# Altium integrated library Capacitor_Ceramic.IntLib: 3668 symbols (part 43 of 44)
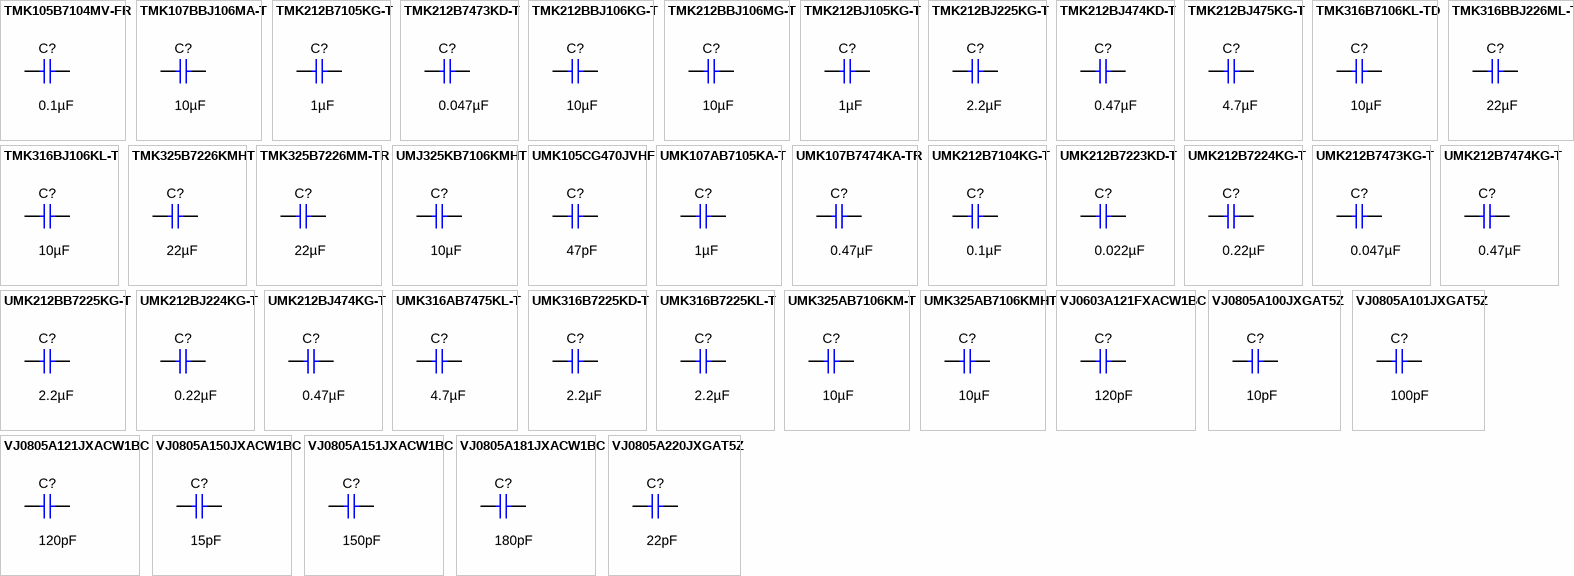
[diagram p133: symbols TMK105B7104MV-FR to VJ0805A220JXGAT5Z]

## UMK212BJ224KG-T
designator C?  ValueDisplayed: 0.22µF  (hidden comment: UMK212BJ224KG-T)
CAP, CERM, 0.22 µF, 50 V,+/- 10%, X5R, 0805; Manufacturer: Taiyo Yuden; Polarized: N; CompType: Capacitor; Value: 0.22uF; U/M: EA; Cap_F: 0.00000022; Tolerance_%: 10; VDC_V: 50; Value2: 50V; TaMin_C: -55; TaMax_C: 85; Cap_Case: 0805; SizeArea_mm2: 2.5; SizeAreaWB_mm2: 6.75; SizeX_mm: 2; SizeY_mm: 1.25; SizeZ_mm: 1.45; AEC Category: Q200; Green_Lifecycle: Active; Green_REACh: Passed
signal-integrity model Cap
simulation model Cap
footprint 0805_HV
footprint 0805_HV1
footprint 0805
footprint 0805M
footprint 0805L
pins: 1, 2

## UMK212BJ474KG-T
designator C?  ValueDisplayed: 0.47µF  (hidden comment: UMK212BJ474KG-T)
CAP, CERM, 0.47 µF, 50 V,+/- 10%, X5R, 0805; Manufacturer: Taiyo Yuden; Polarized: N; CompType: Capacitor; Value: 0.47uF; U/M: EA; Cap_F: 0.00000047; Tolerance_%: 10; VDC_V: 50; Value2: 50V; TaMin_C: -55; TaMax_C: 85; Cap_Case: 0805; SizeArea_mm2: 2.5; SizeAreaWB_mm2: 6.75; SizeX_mm: 2; SizeY_mm: 1.25; SizeZ_mm: 1.45; AEC Category: Q200
signal-integrity model Cap
simulation model Cap
footprint 0805_HV
footprint 0805_HV1
footprint 0805
footprint 0805M
footprint 0805L
pins: 1, 2

## UMK316AB7475KL-T
designator C?  ValueDisplayed: 4.7µF  (hidden comment: UMK316AB7475KL-T)
CAP, CERM, 4.7 µF, 50 V,+/- 10%, X7R, 1206; Manufacturer: Taiyo Yuden; Polarized: N; CompType: Capacitor; Value: 4.7uF; U/M: EA; Cap_F: 0.0000047; Tolerance_%: 10; VDC_V: 50; Value2: 50V; TaMin_C: -55; TaMax_C: 125; Cap_Case: 1206; SizeArea_mm2: 5.12; SizeAreaWB_mm2: 10.92; SizeX_mm: 3.2; SizeY_mm: 1.6; SizeZ_mm: 1.9; AEC Category: Q200; Green_Lifecycle: Active; Green_REACh: Passed
signal-integrity model Cap
simulation model Cap
footprint 1206_190
footprint 1206_190M
footprint 1206_190L
pins: 1, 2

## UMK316B7225KD-T
designator C?  ValueDisplayed: 2.2µF  (hidden comment: UMK316B7225KD-T)
CAP, CERM, 2.2 µF, 50 V,+/- 10%, X7R, 1206; Manufacturer: Taiyo Yuden; Polarized: N; CompType: Capacitor; Value: 2.2uF; U/M: EA; Cap_F: 0.0000022; Tolerance_%: 10; VDC_V: 50; Value2: 50V; TaMin_C: -55; TaMax_C: 125; Cap_Case: 1206; SizeArea_mm2: 5.12; SizeAreaWB_mm2: 10.92; SizeX_mm: 3.2; SizeY_mm: 1.6; SizeZ_mm: 1.35; AEC Category: Q200
signal-integrity model Cap
simulation model Cap
footprint 1206
footprint 1206M
footprint 1206L
pins: 1, 2

## UMK316B7225KL-T
designator C?  ValueDisplayed: 2.2µF  (hidden comment: UMK316B7225KL-T)
CAP, CERM, 2.2 µF, 50 V,+/- 10%, X7R, 1206; Manufacturer: Taiyo Yuden; Polarized: N; CompType: Capacitor; Value: 2.2uF; U/M: EA; Cap_F: 0.0000022; Tolerance_%: 10; VDC_V: 50; Value2: 50V; TaMin_C: -55; TaMax_C: 125; Cap_Case: 1206; SizeArea_mm2: 5.12; SizeAreaWB_mm2: 10.92; SizeX_mm: 3.2; SizeY_mm: 1.6; SizeZ_mm: 1.35; AEC Category: Q200
signal-integrity model Cap
simulation model Cap
footprint 1206
footprint 1206M
footprint 1206L
pins: 1, 2

## UMK325AB7106KM-T
designator C?  ValueDisplayed: 10µF  (hidden comment: UMK325AB7106KM-T)
CAP, CERM, 10 µF, 50 V,+/- 10%, X7R, 1210; Manufacturer: Taiyo Yuden; Polarized: N; CompType: Capacitor; Value: 10uF; U/M: EA; Cap_F: 0.00001; Tolerance_%: 10; VDC_V: 50; Value2: 50V; TaMin_C: -55; TaMax_C: 125; Cap_Case: 1210; SizeArea_mm2: 8; SizeAreaWB_mm2: 14.7; SizeX_mm: 3.2; SizeY_mm: 2.5; SizeZ_mm: 2.8; AEC Category: Q200; Green_Lifecycle: Active; Green_REACh: Passed
signal-integrity model Cap
simulation model Cap
footprint 1210_280
pins: 1, 2

## UMK325AB7106KMHT
designator C?  ValueDisplayed: 10µF  (hidden comment: UMK325AB7106KMHT)
CAP, CERM, 10 µF, 50 V,+/- 10%, X7R, AEC-Q200 Grade 1, 1210; Manufacturer: Taiyo Yuden; Polarized: N; CompType: Capacitor; Value: 10uF; U/M: EA; Cap_F: 0.00001; Tolerance_%: 10; VDC_V: 50; Value2: 50V; TaMin_C: -55; TaMax_C: 125; Cap_Case: 1210; SizeArea_mm2: 8; SizeAreaWB_mm2: 14.7; SizeX_mm: 3.2; SizeY_mm: 2.5; SizeZ_mm: 2.8; AEC Category: Q200; AEC Qualified: Y; AEC Grade: 1
signal-integrity model Cap
simulation model Cap
footprint 1210_280
pins: 1, 2

## VJ0603A121FXACW1BC
designator C?  ValueDisplayed: 120pF  (hidden comment: VJ0603A121FXACW1BC)
CAP, CERM, 120 pF, 50 V,+/- 1%, C0G/NP0, 0603; Manufacturer: Vishay-Sprague; Polarized: N; CompType: Capacitor; Value: 120pF; U/M: EA; Cap_F: 0.00000000012; Tolerance_%: 1; VDC_V: 50; Value2: 50V; TaMin_C: -55; TaMax_C: 125; Cap_Case: 0603; SizeArea_mm2: 1.28; SizeAreaWB_mm2: 4.68; SizeX_mm: 1.6; SizeY_mm: 0.8; AEC Category: Q200
signal-integrity model Cap
simulation model Cap
footprint 0603
footprint 0603M
footprint 0603L
footprint 0603_HV
footprint 0603S
pins: 1, 2

## VJ0805A100JXGAT5Z
designator C?  ValueDisplayed: 10pF  (hidden comment: VJ0805A100JXGAT5Z)
CAP, CERM, 10 pF, 1000 V,+/- 5%, C0G/NP0, 0805; Manufacturer: Vishay-Vitramon; Polarized: N; CompType: Capacitor; Value: 10pF; U/M: EA; Cap_F: 0.00000000001; Tolerance_%: 5; VDC_V: 1000; Value2: 1000V; TaMin_C: -55; TaMax_C: 125; Cap_Case: 0805; SizeArea_mm2: 2.5; SizeAreaWB_mm2: 6.75; SizeX_mm: 2; SizeY_mm: 1.25; SizeZ_mm: 1.45; AEC Category: Q200
signal-integrity model Cap
simulation model Cap
footprint 0805_HV
footprint 0805_HV1
footprint 0805
footprint 0805M
footprint 0805L
pins: 1, 2

## VJ0805A101JXGAT5Z
designator C?  ValueDisplayed: 100pF  (hidden comment: VJ0805A101JXGAT5Z)
CAP, CERM, 100 pF, 1000 V,+/- 5%, C0G/NP0, 0805; Manufacturer: Vishay-Vitramon; Polarized: N; CompType: Capacitor; Value: 100pF; U/M: EA; Cap_F: 0.0000000001; Tolerance_%: 5; VDC_V: 1000; Value2: 1000V; TaMin_C: -55; TaMax_C: 125; Cap_Case: 0805; SizeArea_mm2: 2.5; SizeAreaWB_mm2: 6.75; SizeX_mm: 2; SizeY_mm: 1.25; SizeZ_mm: 1.45; AEC Category: Q200
signal-integrity model Cap
simulation model Cap
footprint 0805_HV
footprint 0805_HV1
footprint 0805
footprint 0805M
footprint 0805L
pins: 1, 2

## VJ0805A121JXACW1BC
designator C?  ValueDisplayed: 120pF  (hidden comment: VJ0805A121JXACW1BC)
CAP, CERM, 120 pF, 50 V,+/- 5%, C0G/NP0, 0805; Manufacturer: Vishay-Bccomponents; Polarized: N; CompType: Capacitor; Value: 120pF; U/M: EA; Cap_F: 0.00000000012; Tolerance_%: 5; VDC_V: 50; Value2: 50V; TaMin_C: -55; TaMax_C: 125; Cap_Case: 0805; SizeArea_mm2: 2.5; SizeAreaWB_mm2: 6.75; SizeX_mm: 2; SizeY_mm: 1.25; SizeZ_mm: 1.45; AEC Category: Q200
signal-integrity model Cap
simulation model Cap
footprint 0805_HV
footprint 0805_HV1
footprint 0805
footprint 0805M
footprint 0805L
pins: 1, 2

## VJ0805A150JXACW1BC
designator C?  ValueDisplayed: 15pF  (hidden comment: VJ0805A150JXACW1BC)
CAP, CERM, 15 pF, 50 V,+/- 5%, C0G/NP0, 0805; Manufacturer: Vishay-Bccomponents; Polarized: N; CompType: Capacitor; Value: 15pF; U/M: EA; Cap_F: 0.000000000015; Tolerance_%: 5; VDC_V: 50; Value2: 50V; TaMin_C: -55; TaMax_C: 125; Cap_Case: 0805; SizeArea_mm2: 2.5; SizeAreaWB_mm2: 6.75; SizeX_mm: 2; SizeY_mm: 1.25; SizeZ_mm: 1.45; AEC Category: Q200
signal-integrity model Cap
simulation model Cap
footprint 0805_HV
footprint 0805_HV1
footprint 0805
footprint 0805M
footprint 0805L
pins: 1, 2

## VJ0805A151JXACW1BC
designator C?  ValueDisplayed: 150pF  (hidden comment: VJ0805A151JXACW1BC)
CAP, CERM, 150 pF, 50 V,+/- 5%, C0G/NP0, 0805; Manufacturer: Vishay-Bccomponents; Polarized: N; CompType: Capacitor; Value: 150pF; U/M: EA; Cap_F: 0.00000000015; Tolerance_%: 5; VDC_V: 50; Value2: 50V; TaMin_C: -55; TaMax_C: 125; Cap_Case: 0805; SizeArea_mm2: 2.5; SizeAreaWB_mm2: 6.75; SizeX_mm: 2; SizeY_mm: 1.25; SizeZ_mm: 1.45; AEC Category: Q200
signal-integrity model Cap
simulation model Cap
footprint 0805_HV
footprint 0805_HV1
footprint 0805
footprint 0805M
footprint 0805L
pins: 1, 2

## VJ0805A181JXACW1BC
designator C?  ValueDisplayed: 180pF  (hidden comment: VJ0805A181JXACW1BC)
CAP, CERM, 180 pF, 50 V,+/- 5%, C0G/NP0, 0805; Manufacturer: Vishay-Bccomponents; Polarized: N; CompType: Capacitor; Value: 180pF; U/M: EA; Cap_F: 0.00000000018; Tolerance_%: 5; VDC_V: 50; Value2: 50V; TaMin_C: -55; TaMax_C: 125; Cap_Case: 0805; SizeArea_mm2: 2.5; SizeAreaWB_mm2: 6.75; SizeX_mm: 2; SizeY_mm: 1.25; SizeZ_mm: 1.45; AEC Category: Q200
signal-integrity model Cap
simulation model Cap
footprint 0805_HV
footprint 0805_HV1
footprint 0805
footprint 0805M
footprint 0805L
pins: 1, 2

## VJ0805A220JXGAT5Z
designator C?  ValueDisplayed: 22pF  (hidden comment: VJ0805A220JXGAT5Z)
CAP, CERM, 22 pF, 1000 V,+/- 5%, C0G/NP0, 0805; Manufacturer: Vishay-Vitramon; Polarized: N; CompType: Capacitor; Value: 22pF; U/M: EA; Cap_F: 0.000000000022; Tolerance_%: 5; VDC_V: 1000; Value2: 1000V; TaMin_C: -55; TaMax_C: 125; Cap_Case: 0805; SizeArea_mm2: 2.5; SizeAreaWB_mm2: 6.75; SizeX_mm: 2; SizeY_mm: 1.25; SizeZ_mm: 1.45; AEC Category: Q200
signal-integrity model Cap
simulation model Cap
footprint 0805_HV
footprint 0805_HV1
footprint 0805
footprint 0805M
footprint 0805L
pins: 1, 2

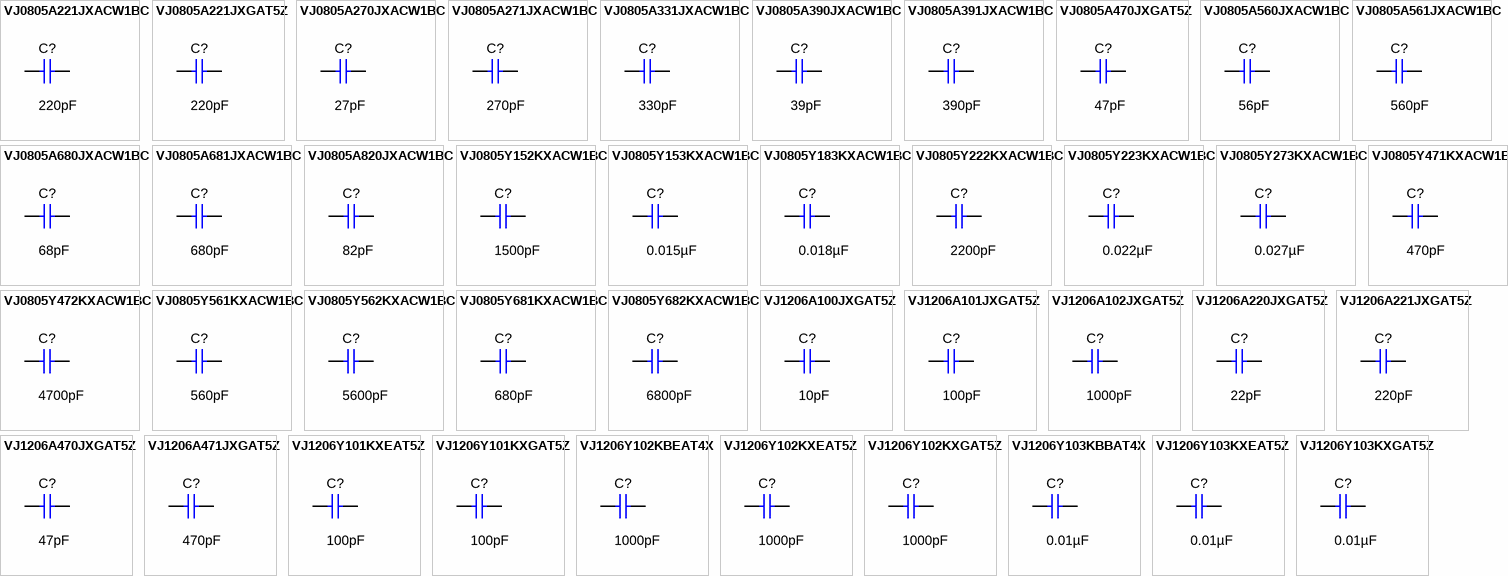
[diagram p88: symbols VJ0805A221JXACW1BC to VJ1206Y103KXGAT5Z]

## VJ0805A221JXACW1BC
designator C?  ValueDisplayed: 220pF  (hidden comment: VJ0805A221JXACW1BC)
CAP, CERM, 220 pF, 50 V,+/- 5%, C0G/NP0, 0805; Manufacturer: Vishay-Bccomponents; Polarized: N; CompType: Capacitor; Value: 220pF; U/M: EA; Cap_F: 0.00000000022; Tolerance_%: 5; VDC_V: 50; Value2: 50V; TaMin_C: -55; TaMax_C: 125; Cap_Case: 0805; SizeArea_mm2: 2.5; SizeAreaWB_mm2: 6.75; SizeX_mm: 2; SizeY_mm: 1.25; SizeZ_mm: 1.45; AEC Category: Q200
signal-integrity model Cap
simulation model Cap
footprint 0805_HV
footprint 0805_HV1
footprint 0805
footprint 0805M
footprint 0805L
pins: 1, 2

## VJ0805A221JXGAT5Z
designator C?  ValueDisplayed: 220pF  (hidden comment: VJ0805A221JXGAT5Z)
CAP, CERM, 220 pF, 1000 V,+/- 5%, C0G/NP0, 0805; Manufacturer: Vishay-Vitramon; Polarized: N; CompType: Capacitor; Value: 220pF; U/M: EA; Cap_F: 0.00000000022; Tolerance_%: 5; VDC_V: 1000; Value2: 1000V; TaMin_C: -55; TaMax_C: 125; Cap_Case: 0805; SizeArea_mm2: 2.5; SizeAreaWB_mm2: 6.75; SizeX_mm: 2; SizeY_mm: 1.25; SizeZ_mm: 1.45; AEC Category: Q200
signal-integrity model Cap
simulation model Cap
footprint 0805_HV
footprint 0805_HV1
footprint 0805
footprint 0805M
footprint 0805L
pins: 1, 2

## VJ0805A270JXACW1BC
designator C?  ValueDisplayed: 27pF  (hidden comment: VJ0805A270JXACW1BC)
CAP, CERM, 27 pF, 50 V,+/- 5%, C0G/NP0, 0805; Manufacturer: Vishay-Bccomponents; Polarized: N; CompType: Capacitor; Value: 27pF; U/M: EA; Cap_F: 0.000000000027; Tolerance_%: 5; VDC_V: 50; Value2: 50V; TaMin_C: -55; TaMax_C: 125; Cap_Case: 0805; SizeArea_mm2: 2.5; SizeAreaWB_mm2: 6.75; SizeX_mm: 2; SizeY_mm: 1.25; SizeZ_mm: 1.45; AEC Category: Q200
signal-integrity model Cap
simulation model Cap
footprint 0805_HV
footprint 0805_HV1
footprint 0805
footprint 0805M
footprint 0805L
pins: 1, 2

## VJ0805A271JXACW1BC
designator C?  ValueDisplayed: 270pF  (hidden comment: VJ0805A271JXACW1BC)
CAP, CERM, 270 pF, 50 V,+/- 5%, C0G/NP0, 0805; Manufacturer: Vishay-Bccomponents; Polarized: N; CompType: Capacitor; Value: 270pF; U/M: EA; Cap_F: 0.00000000027; Tolerance_%: 5; VDC_V: 50; Value2: 50V; TaMin_C: -55; TaMax_C: 125; Cap_Case: 0805; SizeArea_mm2: 2.5; SizeAreaWB_mm2: 6.75; SizeX_mm: 2; SizeY_mm: 1.25; SizeZ_mm: 1.45; AEC Category: Q200; Green_Lifecycle: Not Set; Green_REACh: Incomplete
signal-integrity model Cap
simulation model Cap
footprint 0805_HV
footprint 0805_HV1
footprint 0805
footprint 0805M
footprint 0805L
pins: 1, 2

## VJ0805A331JXACW1BC
designator C?  ValueDisplayed: 330pF  (hidden comment: VJ0805A331JXACW1BC)
CAP, CERM, 330 pF, 50 V,+/- 5%, C0G/NP0, 0805; Manufacturer: Vishay-Bccomponents; Polarized: N; CompType: Capacitor; Value: 330pF; U/M: EA; Cap_F: 0.00000000033; Tolerance_%: 5; VDC_V: 50; Value2: 50V; TaMin_C: -55; TaMax_C: 125; Cap_Case: 0805; SizeArea_mm2: 2.5; SizeAreaWB_mm2: 6.75; SizeX_mm: 2; SizeY_mm: 1.25; SizeZ_mm: 1.45; AEC Category: Q200
signal-integrity model Cap
simulation model Cap
footprint 0805_HV
footprint 0805_HV1
footprint 0805
footprint 0805M
footprint 0805L
pins: 1, 2

## VJ0805A390JXACW1BC
designator C?  ValueDisplayed: 39pF  (hidden comment: VJ0805A390JXACW1BC)
CAP, CERM, 39 pF, 50 V,+/- 5%, C0G/NP0, 0805; Manufacturer: Vishay-Bccomponents; Polarized: N; CompType: Capacitor; Value: 39pF; U/M: EA; Cap_F: 0.000000000039; Tolerance_%: 5; VDC_V: 50; Value2: 50V; TaMin_C: -55; TaMax_C: 125; Cap_Case: 0805; SizeArea_mm2: 2.5; SizeAreaWB_mm2: 6.75; SizeX_mm: 2; SizeY_mm: 1.25; SizeZ_mm: 1.45; AEC Category: Q200
signal-integrity model Cap
simulation model Cap
footprint 0805_HV
footprint 0805_HV1
footprint 0805
footprint 0805M
footprint 0805L
pins: 1, 2

## VJ0805A391JXACW1BC
designator C?  ValueDisplayed: 390pF  (hidden comment: VJ0805A391JXACW1BC)
CAP, CERM, 390 pF, 50 V,+/- 5%, C0G/NP0, 0805; Manufacturer: Vishay-Bccomponents; Polarized: N; CompType: Capacitor; Value: 390pF; U/M: EA; Cap_F: 0.00000000039; Tolerance_%: 5; VDC_V: 50; Value2: 50V; TaMin_C: -55; TaMax_C: 125; Cap_Case: 0805; SizeArea_mm2: 2.5; SizeAreaWB_mm2: 6.75; SizeX_mm: 2; SizeY_mm: 1.25; SizeZ_mm: 1.45; AEC Category: Q200
signal-integrity model Cap
simulation model Cap
footprint 0805_HV
footprint 0805_HV1
footprint 0805
footprint 0805M
footprint 0805L
pins: 1, 2

## VJ0805A470JXGAT5Z
designator C?  ValueDisplayed: 47pF  (hidden comment: VJ0805A470JXGAT5Z)
CAP, CERM, 47 pF, 1000 V,+/- 5%, C0G/NP0, 0805; Manufacturer: Vishay-Vitramon; Polarized: N; CompType: Capacitor; Value: 47pF; U/M: EA; Cap_F: 0.000000000047; Tolerance_%: 5; VDC_V: 1000; Value2: 1000V; TaMin_C: -55; TaMax_C: 125; Cap_Case: 0805; SizeArea_mm2: 2.5; SizeAreaWB_mm2: 6.75; SizeX_mm: 2; SizeY_mm: 1.25; SizeZ_mm: 1.45; AEC Category: Q200
signal-integrity model Cap
simulation model Cap
footprint 0805_HV
footprint 0805_HV1
footprint 0805
footprint 0805M
footprint 0805L
pins: 1, 2

## VJ0805A560JXACW1BC
designator C?  ValueDisplayed: 56pF  (hidden comment: VJ0805A560JXACW1BC)
CAP, CERM, 56 pF, 50 V,+/- 5%, C0G/NP0, 0805; Manufacturer: Vishay-Bccomponents; Polarized: N; CompType: Capacitor; Value: 56pF; U/M: EA; Cap_F: 0.000000000056; Tolerance_%: 5; VDC_V: 50; Value2: 50V; TaMin_C: -55; TaMax_C: 125; Cap_Case: 0805; SizeArea_mm2: 2.5; SizeAreaWB_mm2: 6.75; SizeX_mm: 2; SizeY_mm: 1.25; SizeZ_mm: 1.45; AEC Category: Q200
signal-integrity model Cap
simulation model Cap
footprint 0805_HV
footprint 0805_HV1
footprint 0805
footprint 0805M
footprint 0805L
pins: 1, 2

## VJ0805A561JXACW1BC
designator C?  ValueDisplayed: 560pF  (hidden comment: VJ0805A561JXACW1BC)
CAP, CERM, 560 pF, 50 V,+/- 5%, C0G/NP0, 0805; Manufacturer: Vishay-Bccomponents; Polarized: N; CompType: Capacitor; Value: 560pF; U/M: EA; Cap_F: 0.00000000056; Tolerance_%: 5; VDC_V: 50; Value2: 50V; TaMin_C: -55; TaMax_C: 125; Cap_Case: 0805; SizeArea_mm2: 2.5; SizeAreaWB_mm2: 6.75; SizeX_mm: 2; SizeY_mm: 1.25; SizeZ_mm: 1.45; AEC Category: Q200
signal-integrity model Cap
simulation model Cap
footprint 0805_HV
footprint 0805_HV1
footprint 0805
footprint 0805M
footprint 0805L
pins: 1, 2

## VJ0805A680JXACW1BC
designator C?  ValueDisplayed: 68pF  (hidden comment: VJ0805A680JXACW1BC)
CAP, CERM, 68 pF, 50 V,+/- 5%, C0G/NP0, 0805; Manufacturer: Vishay-Bccomponents; Polarized: N; CompType: Capacitor; Value: 68pF; U/M: EA; Cap_F: 0.000000000068; Tolerance_%: 5; VDC_V: 50; Value2: 50V; TaMin_C: -55; TaMax_C: 125; Cap_Case: 0805; SizeArea_mm2: 2.5; SizeAreaWB_mm2: 6.75; SizeX_mm: 2; SizeY_mm: 1.25; SizeZ_mm: 1.45; AEC Category: Q200
signal-integrity model Cap
simulation model Cap
footprint 0805_HV
footprint 0805_HV1
footprint 0805
footprint 0805M
footprint 0805L
pins: 1, 2

## VJ0805A681JXACW1BC
designator C?  ValueDisplayed: 680pF  (hidden comment: VJ0805A681JXACW1BC)
CAP, CERM, 680 pF, 50 V,+/- 5%, C0G/NP0, 0805; Manufacturer: Vishay-Bccomponents; Polarized: N; CompType: Capacitor; Value: 680pF; U/M: EA; Cap_F: 0.00000000068; Tolerance_%: 5; VDC_V: 50; Value2: 50V; TaMin_C: -55; TaMax_C: 125; Cap_Case: 0805; SizeArea_mm2: 2.5; SizeAreaWB_mm2: 6.75; SizeX_mm: 2; SizeY_mm: 1.25; SizeZ_mm: 1.45; AEC Category: Q200
signal-integrity model Cap
simulation model Cap
footprint 0805_HV
footprint 0805_HV1
footprint 0805
footprint 0805M
footprint 0805L
pins: 1, 2

## VJ0805A820JXACW1BC
designator C?  ValueDisplayed: 82pF  (hidden comment: VJ0805A820JXACW1BC)
CAP, CERM, 82 pF, 50 V,+/- 5%, C0G/NP0, 0805; Manufacturer: Vishay-Bccomponents; Polarized: N; CompType: Capacitor; Value: 82pF; U/M: EA; Cap_F: 0.000000000082; Tolerance_%: 5; VDC_V: 50; Value2: 50V; TaMin_C: -55; TaMax_C: 125; Cap_Case: 0805; SizeArea_mm2: 2.5; SizeAreaWB_mm2: 6.75; SizeX_mm: 2; SizeY_mm: 1.25; SizeZ_mm: 1.45; AEC Category: Q200
signal-integrity model Cap
simulation model Cap
footprint 0805_HV
footprint 0805_HV1
footprint 0805
footprint 0805M
footprint 0805L
pins: 1, 2

## VJ0805Y152KXACW1BC
designator C?  ValueDisplayed: 1500pF  (hidden comment: VJ0805Y152KXACW1BC)
CAP, CERM, 1500 pF, 50 V,+/- 10%, X7R, 0805; Manufacturer: Vishay-Bccomponents; Polarized: N; CompType: Capacitor; Value: 1500pF; U/M: EA; Cap_F: 0.0000000015; Tolerance_%: 10; VDC_V: 50; Value2: 50V; TaMin_C: -55; TaMax_C: 125; Cap_Case: 0805; SizeArea_mm2: 2.5; SizeAreaWB_mm2: 6.75; SizeX_mm: 2; SizeY_mm: 1.25; SizeZ_mm: 1.45; AEC Category: Q200
signal-integrity model Cap
simulation model Cap
footprint 0805_HV
footprint 0805_HV1
footprint 0805
footprint 0805M
footprint 0805L
pins: 1, 2

## VJ0805Y153KXACW1BC
designator C?  ValueDisplayed: 0.015µF  (hidden comment: VJ0805Y153KXACW1BC)
CAP, CERM, 0.015 µF, 50 V,+/- 10%, X7R, 0805; Manufacturer: Vishay-Bccomponents; Polarized: N; CompType: Capacitor; Value: 0.015uF; U/M: EA; Cap_F: 0.000000015; Tolerance_%: 10; VDC_V: 50; Value2: 50V; TaMin_C: -55; TaMax_C: 125; Cap_Case: 0805; SizeArea_mm2: 2.5; SizeAreaWB_mm2: 6.75; SizeX_mm: 2; SizeY_mm: 1.25; SizeZ_mm: 1.45; AEC Category: Q200
signal-integrity model Cap
simulation model Cap
footprint 0805_HV
footprint 0805_HV1
footprint 0805
footprint 0805M
footprint 0805L
pins: 1, 2

## VJ0805Y183KXACW1BC
designator C?  ValueDisplayed: 0.018µF  (hidden comment: VJ0805Y183KXACW1BC)
CAP, CERM, 0.018 µF, 50 V,+/- 10%, X7R, 0805; Manufacturer: Vishay-Bccomponents; Polarized: N; CompType: Capacitor; Value: 0.018uF; U/M: EA; Cap_F: 0.000000018; Tolerance_%: 10; VDC_V: 50; Value2: 50V; TaMin_C: -55; TaMax_C: 125; Cap_Case: 0805; SizeArea_mm2: 2.5; SizeAreaWB_mm2: 6.75; SizeX_mm: 2; SizeY_mm: 1.25; SizeZ_mm: 1.45; AEC Category: Q200
signal-integrity model Cap
simulation model Cap
footprint 0805_HV
footprint 0805_HV1
footprint 0805
footprint 0805M
footprint 0805L
pins: 1, 2

## VJ0805Y222KXACW1BC
designator C?  ValueDisplayed: 2200pF  (hidden comment: VJ0805Y222KXACW1BC)
CAP, CERM, 2200 pF, 50 V,+/- 10%, X7R, 0805; Manufacturer: Vishay-Bccomponents; Polarized: N; CompType: Capacitor; Value: 2200pF; U/M: EA; Cap_F: 0.0000000022; Tolerance_%: 10; VDC_V: 50; Value2: 50V; TaMin_C: -55; TaMax_C: 125; Cap_Case: 0805; SizeArea_mm2: 2.5; SizeAreaWB_mm2: 6.75; SizeX_mm: 2; SizeY_mm: 1.25; SizeZ_mm: 1.45; AEC Category: Q200
signal-integrity model Cap
simulation model Cap
footprint 0805_HV
footprint 0805_HV1
footprint 0805
footprint 0805M
footprint 0805L
pins: 1, 2

## VJ0805Y223KXACW1BC
designator C?  ValueDisplayed: 0.022µF  (hidden comment: VJ0805Y223KXACW1BC)
CAP, CERM, 0.022 µF, 50 V,+/- 10%, X7R, 0805; Manufacturer: Vishay-Bccomponents; Polarized: N; CompType: Capacitor; Value: 0.022uF; U/M: EA; Cap_F: 0.000000022; Tolerance_%: 10; VDC_V: 50; Value2: 50V; TaMin_C: -55; TaMax_C: 125; Cap_Case: 0805; SizeArea_mm2: 2.5; SizeAreaWB_mm2: 6.75; SizeX_mm: 2; SizeY_mm: 1.25; SizeZ_mm: 1.45; AEC Category: Q200
signal-integrity model Cap
simulation model Cap
footprint 0805_HV
footprint 0805_HV1
footprint 0805
footprint 0805M
footprint 0805L
pins: 1, 2

## VJ0805Y273KXACW1BC
designator C?  ValueDisplayed: 0.027µF  (hidden comment: VJ0805Y273KXACW1BC)
CAP, CERM, 0.027 µF, 50 V,+/- 10%, X7R, 0805; Manufacturer: Vishay-Bccomponents; Polarized: N; CompType: Capacitor; Value: 0.027uF; U/M: EA; Cap_F: 0.000000027; Tolerance_%: 10; VDC_V: 50; Value2: 50V; TaMin_C: -55; TaMax_C: 125; Cap_Case: 0805; SizeArea_mm2: 2.5; SizeAreaWB_mm2: 6.75; SizeX_mm: 2; SizeY_mm: 1.25; SizeZ_mm: 1.45; AEC Category: Q200
signal-integrity model Cap
simulation model Cap
footprint 0805_HV
footprint 0805_HV1
footprint 0805
footprint 0805M
footprint 0805L
pins: 1, 2

## VJ0805Y471KXACW1BC
designator C?  ValueDisplayed: 470pF  (hidden comment: VJ0805Y471KXACW1BC)
CAP, CERM, 470 pF, 50 V,+/- 10%, X7R, 0805; Manufacturer: Vishay-Bccomponents; Polarized: N; CompType: Capacitor; Value: 470pF; U/M: EA; Cap_F: 0.00000000047; Tolerance_%: 10; VDC_V: 50; Value2: 50V; TaMin_C: -55; TaMax_C: 125; Cap_Case: 0805; SizeArea_mm2: 2.5; SizeAreaWB_mm2: 6.75; SizeX_mm: 2; SizeY_mm: 1.25; SizeZ_mm: 1.45; AEC Category: Q200
signal-integrity model Cap
simulation model Cap
footprint 0805_HV
footprint 0805_HV1
footprint 0805
footprint 0805M
footprint 0805L
pins: 1, 2

## VJ0805Y472KXACW1BC
designator C?  ValueDisplayed: 4700pF  (hidden comment: VJ0805Y472KXACW1BC)
CAP, CERM, 4700 pF, 50 V,+/- 10%, X7R, 0805; Manufacturer: Vishay-Bccomponents; Polarized: N; CompType: Capacitor; Value: 4700pF; U/M: EA; Cap_F: 0.0000000047; Tolerance_%: 10; VDC_V: 50; Value2: 50V; TaMin_C: -55; TaMax_C: 125; Cap_Case: 0805; SizeArea_mm2: 2.5; SizeAreaWB_mm2: 6.75; SizeX_mm: 2; SizeY_mm: 1.25; SizeZ_mm: 1.45; AEC Category: Q200
signal-integrity model Cap
simulation model Cap
footprint 0805_HV
footprint 0805_HV1
footprint 0805
footprint 0805M
footprint 0805L
pins: 1, 2

## VJ0805Y561KXACW1BC
designator C?  ValueDisplayed: 560pF  (hidden comment: VJ0805Y561KXACW1BC)
CAP, CERM, 560 pF, 50 V,+/- 10%, X7R, 0805; Manufacturer: Vishay-Bccomponents; Polarized: N; CompType: Capacitor; Value: 560pF; U/M: EA; Cap_F: 0.00000000056; Tolerance_%: 10; VDC_V: 50; Value2: 50V; TaMin_C: -55; TaMax_C: 125; Cap_Case: 0805; SizeArea_mm2: 2.5; SizeAreaWB_mm2: 6.75; SizeX_mm: 2; SizeY_mm: 1.25; SizeZ_mm: 1.45; AEC Category: Q200; Green_Lifecycle: Active; Green_REACh: Passed
signal-integrity model Cap
simulation model Cap
footprint 0805_HV
footprint 0805_HV1
footprint 0805
footprint 0805M
footprint 0805L
pins: 1, 2

## VJ0805Y562KXACW1BC
designator C?  ValueDisplayed: 5600pF  (hidden comment: VJ0805Y562KXACW1BC)
CAP, CERM, 5600 pF, 50 V,+/- 10%, X7R, 0805; Manufacturer: Vishay-Bccomponents; Polarized: N; CompType: Capacitor; Value: 5600pF; U/M: EA; Cap_F: 0.0000000056; Tolerance_%: 10; VDC_V: 50; Value2: 50V; TaMin_C: -55; TaMax_C: 125; Cap_Case: 0805; SizeArea_mm2: 2.5; SizeAreaWB_mm2: 6.75; SizeX_mm: 2; SizeY_mm: 1.25; SizeZ_mm: 1.45; AEC Category: Q200
signal-integrity model Cap
simulation model Cap
footprint 0805_HV
footprint 0805_HV1
footprint 0805
footprint 0805M
footprint 0805L
pins: 1, 2

## VJ0805Y681KXACW1BC
designator C?  ValueDisplayed: 680pF  (hidden comment: VJ0805Y681KXACW1BC)
CAP, CERM, 680 pF, 50 V,+/- 10%, X7R, 0805; Manufacturer: Vishay-Bccomponents; Polarized: N; CompType: Capacitor; Value: 680pF; U/M: EA; Cap_F: 0.00000000068; Tolerance_%: 10; VDC_V: 50; Value2: 50V; TaMin_C: -55; TaMax_C: 125; Cap_Case: 0805; SizeArea_mm2: 2.5; SizeAreaWB_mm2: 6.75; SizeX_mm: 2; SizeY_mm: 1.25; SizeZ_mm: 1.45; AEC Category: Q200
signal-integrity model Cap
simulation model Cap
footprint 0805_HV
footprint 0805_HV1
footprint 0805
footprint 0805M
footprint 0805L
pins: 1, 2

## VJ0805Y682KXACW1BC
designator C?  ValueDisplayed: 6800pF  (hidden comment: VJ0805Y682KXACW1BC)
CAP, CERM, 6800 pF, 50 V,+/- 10%, X7R, 0805; Manufacturer: Vishay-Bccomponents; Polarized: N; CompType: Capacitor; Value: 6800pF; U/M: EA; Cap_F: 0.0000000068; Tolerance_%: 10; VDC_V: 50; Value2: 50V; TaMin_C: -55; TaMax_C: 125; Cap_Case: 0805; SizeArea_mm2: 2.5; SizeAreaWB_mm2: 6.75; SizeX_mm: 2; SizeY_mm: 1.25; SizeZ_mm: 1.45; AEC Category: Q200
signal-integrity model Cap
simulation model Cap
footprint 0805_HV
footprint 0805_HV1
footprint 0805
footprint 0805M
footprint 0805L
pins: 1, 2

## VJ1206A100JXGAT5Z
designator C?  ValueDisplayed: 10pF  (hidden comment: VJ1206A100JXGAT5Z)
CAP, CERM, 10 pF, 1000 V,+/- 5%, C0G/NP0, 1206; Manufacturer: Vishay-Vitramon; Polarized: N; CompType: Capacitor; Value: 10pF; U/M: EA; Cap_F: 0.00000000001; Tolerance_%: 5; VDC_V: 1000; Value2: 1000V; TaMin_C: -55; TaMax_C: 125; Cap_Case: 1206; SizeArea_mm2: 5.12; SizeAreaWB_mm2: 10.92; SizeX_mm: 3.2; SizeY_mm: 1.6; SizeZ_mm: 1.35; AEC Category: Q200
signal-integrity model Cap
simulation model Cap
footprint 1206
footprint 1206M
footprint 1206L
pins: 1, 2

## VJ1206A101JXGAT5Z
designator C?  ValueDisplayed: 100pF  (hidden comment: VJ1206A101JXGAT5Z)
CAP, CERM, 100 pF, 1000 V,+/- 5%, C0G/NP0, 1206; Manufacturer: Vishay-Vitramon; Polarized: N; CompType: Capacitor; Value: 100pF; U/M: EA; Cap_F: 0.0000000001; Tolerance_%: 5; VDC_V: 1000; Value2: 1000V; TaMin_C: -55; TaMax_C: 125; Cap_Case: 1206; SizeArea_mm2: 5.12; SizeAreaWB_mm2: 10.92; SizeX_mm: 3.2; SizeY_mm: 1.6; SizeZ_mm: 1.35; AEC Category: Q200
signal-integrity model Cap
simulation model Cap
footprint 1206
footprint 1206M
footprint 1206L
pins: 1, 2

## VJ1206A102JXGAT5Z
designator C?  ValueDisplayed: 1000pF  (hidden comment: VJ1206A102JXGAT5Z)
CAP, CERM, 1000 pF, 1000 V,+/- 5%, C0G/NP0, 1206; Manufacturer: Vishay-Vitramon; Polarized: N; CompType: Capacitor; Value: 1000pF; U/M: EA; Cap_F: 0.000000001; Tolerance_%: 5; VDC_V: 1000; Value2: 1000V; TaMin_C: -55; TaMax_C: 125; Cap_Case: 1206; SizeArea_mm2: 5.12; SizeAreaWB_mm2: 10.92; SizeX_mm: 3.2; SizeY_mm: 1.6; SizeZ_mm: 1.35; AEC Category: Q200
signal-integrity model Cap
simulation model Cap
footprint 1206
footprint 1206M
footprint 1206L
pins: 1, 2

## VJ1206A220JXGAT5Z
designator C?  ValueDisplayed: 22pF  (hidden comment: VJ1206A220JXGAT5Z)
CAP, CERM, 22 pF, 1000 V,+/- 5%, C0G/NP0, 1206; Manufacturer: Vishay-Vitramon; Polarized: N; CompType: Capacitor; Value: 22pF; U/M: EA; Cap_F: 0.000000000022; Tolerance_%: 5; VDC_V: 1000; Value2: 1000V; TaMin_C: -55; TaMax_C: 125; Cap_Case: 1206; SizeArea_mm2: 5.12; SizeAreaWB_mm2: 10.92; SizeX_mm: 3.2; SizeY_mm: 1.6; SizeZ_mm: 1.35; AEC Category: Q200
signal-integrity model Cap
simulation model Cap
footprint 1206
footprint 1206M
footprint 1206L
pins: 1, 2

## VJ1206A221JXGAT5Z
designator C?  ValueDisplayed: 220pF  (hidden comment: VJ1206A221JXGAT5Z)
CAP, CERM, 220 pF, 1000 V,+/- 5%, C0G/NP0, 1206; Manufacturer: Vishay-Vitramon; Polarized: N; CompType: Capacitor; Value: 220pF; U/M: EA; Cap_F: 0.00000000022; Tolerance_%: 5; VDC_V: 1000; Value2: 1000V; TaMin_C: -55; TaMax_C: 125; Cap_Case: 1206; SizeArea_mm2: 5.12; SizeAreaWB_mm2: 10.92; SizeX_mm: 3.2; SizeY_mm: 1.6; SizeZ_mm: 1.35; AEC Category: Q200
signal-integrity model Cap
simulation model Cap
footprint 1206
footprint 1206M
footprint 1206L
pins: 1, 2

## VJ1206A470JXGAT5Z
designator C?  ValueDisplayed: 47pF  (hidden comment: VJ1206A470JXGAT5Z)
CAP, CERM, 47 pF, 1000 V,+/- 5%, C0G/NP0, 1206; Manufacturer: Vishay-Vitramon; Polarized: N; CompType: Capacitor; Value: 47pF; U/M: EA; Cap_F: 0.000000000047; Tolerance_%: 5; VDC_V: 1000; Value2: 1000V; TaMin_C: -55; TaMax_C: 125; Cap_Case: 1206; SizeArea_mm2: 5.12; SizeAreaWB_mm2: 10.92; SizeX_mm: 3.2; SizeY_mm: 1.6; SizeZ_mm: 1.35; AEC Category: Q200
signal-integrity model Cap
simulation model Cap
footprint 1206
footprint 1206M
footprint 1206L
pins: 1, 2

## VJ1206A471JXGAT5Z
designator C?  ValueDisplayed: 470pF  (hidden comment: VJ1206A471JXGAT5Z)
CAP, CERM, 470 pF, 1000 V,+/- 5%, C0G/NP0, 1206; Manufacturer: Vishay-Vitramon; Polarized: N; CompType: Capacitor; Value: 470pF; U/M: EA; Cap_F: 0.00000000047; Tolerance_%: 5; VDC_V: 1000; Value2: 1000V; TaMin_C: -55; TaMax_C: 125; Cap_Case: 1206; SizeArea_mm2: 5.12; SizeAreaWB_mm2: 10.92; SizeX_mm: 3.2; SizeY_mm: 1.6; SizeZ_mm: 1.35; AEC Category: Q200
signal-integrity model Cap
simulation model Cap
footprint 1206
footprint 1206M
footprint 1206L
pins: 1, 2

## VJ1206Y101KXEAT5Z
designator C?  ValueDisplayed: 100pF  (hidden comment: VJ1206Y101KXEAT5Z)
CAP, CERM, 100 pF, 500 V,+/- 10%, X7R, 1206; Manufacturer: Vishay-Vitramon; Polarized: N; CompType: Capacitor; Value: 100pF; U/M: EA; Cap_F: 0.0000000001; Tolerance_%: 10; VDC_V: 500; Value2: 500V; TaMin_C: -55; TaMax_C: 125; Cap_Case: 1206; SizeArea_mm2: 5.12; SizeAreaWB_mm2: 10.92; SizeX_mm: 3.2; SizeY_mm: 1.6; SizeZ_mm: 1.35; AEC Category: Q200
signal-integrity model Cap
simulation model Cap
footprint 1206
footprint 1206M
footprint 1206L
pins: 1, 2

## VJ1206Y101KXGAT5Z
designator C?  ValueDisplayed: 100pF  (hidden comment: VJ1206Y101KXGAT5Z)
CAP, CERM, 100 pF, 1000 V,+/- 10%, X7R, 1206; Manufacturer: Vishay-Vitramon; Polarized: N; CompType: Capacitor; Value: 100pF; U/M: EA; Cap_F: 0.0000000001; Tolerance_%: 10; VDC_V: 1000; Value2: 1000V; TaMin_C: -55; TaMax_C: 125; Cap_Case: 1206; SizeArea_mm2: 5.12; SizeAreaWB_mm2: 10.92; SizeX_mm: 3.2; SizeY_mm: 1.6; SizeZ_mm: 1.35; AEC Category: Q200
signal-integrity model Cap
simulation model Cap
footprint 1206
footprint 1206M
footprint 1206L
pins: 1, 2

## VJ1206Y102KBEAT4X
designator C?  ValueDisplayed: 1000pF  (hidden comment: VJ1206Y102KBEAT4X)
CAP, CERM, 1000 pF, 500 V,+/- 10%, X7R, 1206; Manufacturer: Vishay-Vitramon; Polarized: N; CompType: Capacitor; Value: 1000pF; U/M: EA; Cap_F: 0.000000001; Tolerance_%: 10; VDC_V: 500; Value2: 500V; TaMin_C: -55; TaMax_C: 125; Cap_Case: 1206; SizeArea_mm2: 5.12; SizeAreaWB_mm2: 10.92; SizeX_mm: 3.2; SizeY_mm: 1.6; SizeZ_mm: 1.35; AEC Category: Q200
signal-integrity model Cap
simulation model Cap
footprint 1206
footprint 1206M
footprint 1206L
pins: 1, 2

## VJ1206Y102KXEAT5Z
designator C?  ValueDisplayed: 1000pF  (hidden comment: VJ1206Y102KXEAT5Z)
CAP, CERM, 1000 pF, 500 V,+/- 10%, X7R, 1206; Manufacturer: Vishay-Vitramon; Polarized: N; CompType: Capacitor; Value: 1000pF; U/M: EA; Cap_F: 0.000000001; Tolerance_%: 10; VDC_V: 500; Value2: 500V; TaMin_C: -55; TaMax_C: 125; Cap_Case: 1206; SizeArea_mm2: 5.12; SizeAreaWB_mm2: 10.92; SizeX_mm: 3.2; SizeY_mm: 1.6; SizeZ_mm: 1.35; AEC Category: Q200
signal-integrity model Cap
simulation model Cap
footprint 1206
footprint 1206M
footprint 1206L
pins: 1, 2

## VJ1206Y102KXGAT5Z
designator C?  ValueDisplayed: 1000pF  (hidden comment: VJ1206Y102KXGAT5Z)
CAP, CERM, 1000 pF, 1000 V,+/- 10%, X7R, 1206; Manufacturer: Vishay-Vitramon; Polarized: N; CompType: Capacitor; Value: 1000pF; U/M: EA; Cap_F: 0.000000001; Tolerance_%: 10; VDC_V: 1000; Value2: 1000V; TaMin_C: -55; TaMax_C: 125; Cap_Case: 1206; SizeArea_mm2: 5.12; SizeAreaWB_mm2: 10.92; SizeX_mm: 3.2; SizeY_mm: 1.6; SizeZ_mm: 1.35; AEC Category: Q200
signal-integrity model Cap
simulation model Cap
footprint 1206
footprint 1206M
footprint 1206L
pins: 1, 2

## VJ1206Y103KBBAT4X
designator C?  ValueDisplayed: 0.01µF  (hidden comment: VJ1206Y103KBBAT4X)
CAP, CERM, 0.01 µF, 100 V,+/- 10%, X7R, 1206; Manufacturer: Vishay-Vitramon; Polarized: N; CompType: Capacitor; Value: 0.01uF; U/M: EA; Cap_F: 0.00000001; Tolerance_%: 10; VDC_V: 100; Value2: 100V; TaMin_C: -55; TaMax_C: 125; Cap_Case: 1206; SizeArea_mm2: 5.12; SizeAreaWB_mm2: 10.92; SizeX_mm: 3.2; SizeY_mm: 1.6; SizeZ_mm: 1.35; AEC Category: Q200
signal-integrity model Cap
simulation model Cap
footprint 1206
footprint 1206M
footprint 1206L
pins: 1, 2

## VJ1206Y103KXEAT5Z
designator C?  ValueDisplayed: 0.01µF  (hidden comment: VJ1206Y103KXEAT5Z)
CAP, CERM, 0.01 µF, 500 V,+/- 10%, X7R, 1206; Manufacturer: Vishay-Vitramon; Polarized: N; CompType: Capacitor; Value: 0.01uF; U/M: EA; Cap_F: 0.00000001; Tolerance_%: 10; VDC_V: 500; Value2: 500V; TaMin_C: -55; TaMax_C: 125; Cap_Case: 1206; SizeArea_mm2: 5.12; SizeAreaWB_mm2: 10.92; SizeX_mm: 3.2; SizeY_mm: 1.6; SizeZ_mm: 1.35; AEC Category: Q200
signal-integrity model Cap
simulation model Cap
footprint 1206
footprint 1206M
footprint 1206L
pins: 1, 2

## VJ1206Y103KXGAT5Z
designator C?  ValueDisplayed: 0.01µF  (hidden comment: VJ1206Y103KXGAT5Z)
CAP, CERM, 0.01 µF, 1000 V,+/- 10%, X7R, 1206; Manufacturer: Vishay-Vitramon; Polarized: N; CompType: Capacitor; Value: 0.01uF; U/M: EA; Cap_F: 0.00000001; Tolerance_%: 10; VDC_V: 1000; Value2: 1000V; TaMin_C: -55; TaMax_C: 125; Cap_Case: 1206; SizeArea_mm2: 5.12; SizeAreaWB_mm2: 10.92; SizeX_mm: 3.2; SizeY_mm: 1.6; SizeZ_mm: 1.35; AEC Category: Q200
signal-integrity model Cap
simulation model Cap
footprint 1206
footprint 1206M
footprint 1206L
pins: 1, 2

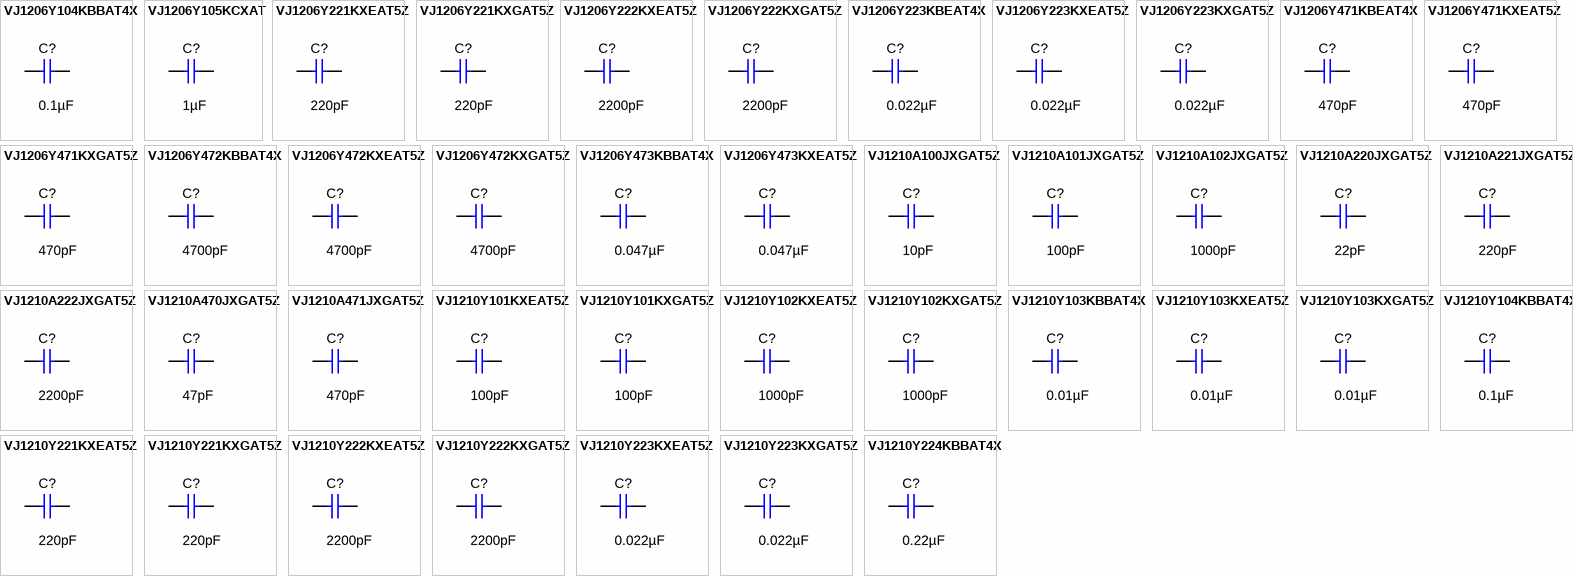
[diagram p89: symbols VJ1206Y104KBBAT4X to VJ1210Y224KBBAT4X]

## VJ1206Y104KBBAT4X
designator C?  ValueDisplayed: 0.1µF  (hidden comment: VJ1206Y104KBBAT4X)
CAP, CERM, 0.1 µF, 100 V,+/- 10%, X7R, 1206; Manufacturer: Vishay-Vitramon; Polarized: N; CompType: Capacitor; Value: 0.1uF; U/M: EA; Cap_F: 0.0000001; Tolerance_%: 10; VDC_V: 100; Value2: 100V; TaMin_C: -55; TaMax_C: 125; Cap_Case: 1206; SizeArea_mm2: 5.12; SizeAreaWB_mm2: 10.92; SizeX_mm: 3.2; SizeY_mm: 1.6; SizeZ_mm: 1.35; AEC Category: Q200
signal-integrity model Cap
simulation model Cap
footprint 1206
footprint 1206M
footprint 1206L
pins: 1, 2

## VJ1206Y105KCXAT
designator C?  ValueDisplayed: 1µF  (hidden comment: VJ1206Y105KCXAT)
CAP, CERM, 1 µF, 25 V,+/- 10%, X7R, 1206; Manufacturer: Vishay-Vitramon; Polarized: N; CompType: Capacitor; Value: 1uF; U/M: EA; Cap_F: 0.000001; Tolerance_%: 10; VDC_V: 25; Value2: 25V; TaMin_C: -55; TaMax_C: 125; Cap_Case: 1206; SizeArea_mm2: 5.12; SizeAreaWB_mm2: 10.92; SizeX_mm: 3.2; SizeY_mm: 1.6; SizeZ_mm: 1.8; AEC Category: Q200
signal-integrity model Cap
simulation model Cap
footprint 1206_180
footprint 1206_180M
footprint 1206_180L
pins: 1, 2

## VJ1206Y221KXEAT5Z
designator C?  ValueDisplayed: 220pF  (hidden comment: VJ1206Y221KXEAT5Z)
CAP, CERM, 220 pF, 500 V,+/- 10%, X7R, 1206; Manufacturer: Vishay-Vitramon; Polarized: N; CompType: Capacitor; Value: 220pF; U/M: EA; Cap_F: 0.00000000022; Tolerance_%: 10; VDC_V: 500; Value2: 500V; TaMin_C: -55; TaMax_C: 125; Cap_Case: 1206; SizeArea_mm2: 5.12; SizeAreaWB_mm2: 10.92; SizeX_mm: 3.2; SizeY_mm: 1.6; SizeZ_mm: 1.35; AEC Category: Q200
signal-integrity model Cap
simulation model Cap
footprint 1206
footprint 1206M
footprint 1206L
pins: 1, 2

## VJ1206Y221KXGAT5Z
designator C?  ValueDisplayed: 220pF  (hidden comment: VJ1206Y221KXGAT5Z)
CAP, CERM, 220 pF, 1000 V,+/- 10%, X7R, 1206; Manufacturer: Vishay-Vitramon; Polarized: N; CompType: Capacitor; Value: 220pF; U/M: EA; Cap_F: 0.00000000022; Tolerance_%: 10; VDC_V: 1000; Value2: 1000V; TaMin_C: -55; TaMax_C: 125; Cap_Case: 1206; SizeArea_mm2: 5.12; SizeAreaWB_mm2: 10.92; SizeX_mm: 3.2; SizeY_mm: 1.6; SizeZ_mm: 1.35; AEC Category: Q200
signal-integrity model Cap
simulation model Cap
footprint 1206
footprint 1206M
footprint 1206L
pins: 1, 2

## VJ1206Y222KXEAT5Z
designator C?  ValueDisplayed: 2200pF  (hidden comment: VJ1206Y222KXEAT5Z)
CAP, CERM, 2200 pF, 500 V,+/- 10%, X7R, 1206; Manufacturer: Vishay-Vitramon; Polarized: N; CompType: Capacitor; Value: 2200pF; U/M: EA; Cap_F: 0.0000000022; Tolerance_%: 10; VDC_V: 500; Value2: 500V; TaMin_C: -55; TaMax_C: 125; Cap_Case: 1206; SizeArea_mm2: 5.12; SizeAreaWB_mm2: 10.92; SizeX_mm: 3.2; SizeY_mm: 1.6; SizeZ_mm: 1.35; AEC Category: Q200
signal-integrity model Cap
simulation model Cap
footprint 1206
footprint 1206M
footprint 1206L
pins: 1, 2

## VJ1206Y222KXGAT5Z
designator C?  ValueDisplayed: 2200pF  (hidden comment: VJ1206Y222KXGAT5Z)
CAP, CERM, 2200 pF, 1000 V,+/- 10%, X7R, 1206; Manufacturer: Vishay-Vitramon; Polarized: N; CompType: Capacitor; Value: 2200pF; U/M: EA; Cap_F: 0.0000000022; Tolerance_%: 10; VDC_V: 1000; Value2: 1000V; TaMin_C: -55; TaMax_C: 125; Cap_Case: 1206; SizeArea_mm2: 5.12; SizeAreaWB_mm2: 10.92; SizeX_mm: 3.2; SizeY_mm: 1.6; SizeZ_mm: 1.35; AEC Category: Q200
signal-integrity model Cap
simulation model Cap
footprint 1206
footprint 1206M
footprint 1206L
pins: 1, 2

## VJ1206Y223KBEAT4X
designator C?  ValueDisplayed: 0.022µF  (hidden comment: VJ1206Y223KBEAT4X)
CAP, CERM, 0.022 µF, 500 V,+/- 10%, X7R, 1206; Manufacturer: Vishay-Vitramon; Polarized: N; CompType: Capacitor; Value: 0.022uF; U/M: EA; Cap_F: 0.000000022; Tolerance_%: 10; VDC_V: 500; Value2: 500V; TaMin_C: -55; TaMax_C: 125; Cap_Case: 1206; SizeArea_mm2: 5.12; SizeAreaWB_mm2: 10.92; SizeX_mm: 3.2; SizeY_mm: 1.6; SizeZ_mm: 1.35; AEC Category: Q200
signal-integrity model Cap
simulation model Cap
footprint 1206
footprint 1206M
footprint 1206L
pins: 1, 2

## VJ1206Y223KXEAT5Z
designator C?  ValueDisplayed: 0.022µF  (hidden comment: VJ1206Y223KXEAT5Z)
CAP, CERM, 0.022 µF, 500 V,+/- 10%, X7R, 1206; Manufacturer: Vishay-Vitramon; Polarized: N; CompType: Capacitor; Value: 0.022uF; U/M: EA; Cap_F: 0.000000022; Tolerance_%: 10; VDC_V: 500; Value2: 500V; TaMin_C: -55; TaMax_C: 125; Cap_Case: 1206; SizeArea_mm2: 5.12; SizeAreaWB_mm2: 10.92; SizeX_mm: 3.2; SizeY_mm: 1.6; SizeZ_mm: 1.35; AEC Category: Q200
signal-integrity model Cap
simulation model Cap
footprint 1206
footprint 1206M
footprint 1206L
pins: 1, 2

## VJ1206Y223KXGAT5Z
designator C?  ValueDisplayed: 0.022µF  (hidden comment: VJ1206Y223KXGAT5Z)
CAP, CERM, 0.022 µF, 1000 V,+/- 10%, X7R, 1206; Manufacturer: Vishay-Vitramon; Polarized: N; CompType: Capacitor; Value: 0.022uF; U/M: EA; Cap_F: 0.000000022; Tolerance_%: 10; VDC_V: 1000; Value2: 1000V; TaMin_C: -55; TaMax_C: 125; Cap_Case: 1206; SizeArea_mm2: 5.12; SizeAreaWB_mm2: 10.92; SizeX_mm: 3.2; SizeY_mm: 1.6; SizeZ_mm: 1.35; AEC Category: Q200
signal-integrity model Cap
simulation model Cap
footprint 1206
footprint 1206M
footprint 1206L
pins: 1, 2

## VJ1206Y471KBEAT4X
designator C?  ValueDisplayed: 470pF  (hidden comment: VJ1206Y471KBEAT4X)
CAP, CERM, 470 pF, 500 V,+/- 10%, X7R, 1206; Manufacturer: Vishay-Vitramon; Polarized: N; CompType: Capacitor; Value: 470pF; U/M: EA; Cap_F: 0.00000000047; Tolerance_%: 10; VDC_V: 500; Value2: 500V; TaMin_C: -55; TaMax_C: 125; Cap_Case: 1206; SizeArea_mm2: 5.12; SizeAreaWB_mm2: 10.92; SizeX_mm: 3.2; SizeY_mm: 1.6; SizeZ_mm: 1.35; AEC Category: Q200
signal-integrity model Cap
simulation model Cap
footprint 1206
footprint 1206M
footprint 1206L
pins: 1, 2

## VJ1206Y471KXEAT5Z
designator C?  ValueDisplayed: 470pF  (hidden comment: VJ1206Y471KXEAT5Z)
CAP, CERM, 470 pF, 500 V,+/- 10%, X7R, 1206; Manufacturer: Vishay-Vitramon; Polarized: N; CompType: Capacitor; Value: 470pF; U/M: EA; Cap_F: 0.00000000047; Tolerance_%: 10; VDC_V: 500; Value2: 500V; TaMin_C: -55; TaMax_C: 125; Cap_Case: 1206; SizeArea_mm2: 5.12; SizeAreaWB_mm2: 10.92; SizeX_mm: 3.2; SizeY_mm: 1.6; SizeZ_mm: 1.35; AEC Category: Q200
signal-integrity model Cap
simulation model Cap
footprint 1206
footprint 1206M
footprint 1206L
pins: 1, 2

## VJ1206Y471KXGAT5Z
designator C?  ValueDisplayed: 470pF  (hidden comment: VJ1206Y471KXGAT5Z)
CAP, CERM, 470 pF, 1000 V,+/- 10%, X7R, 1206; Manufacturer: Vishay-Vitramon; Polarized: N; CompType: Capacitor; Value: 470pF; U/M: EA; Cap_F: 0.00000000047; Tolerance_%: 10; VDC_V: 1000; Value2: 1000V; TaMin_C: -55; TaMax_C: 125; Cap_Case: 1206; SizeArea_mm2: 5.12; SizeAreaWB_mm2: 10.92; SizeX_mm: 3.2; SizeY_mm: 1.6; SizeZ_mm: 1.35; AEC Category: Q200
signal-integrity model Cap
simulation model Cap
footprint 1206
footprint 1206M
footprint 1206L
pins: 1, 2

## VJ1206Y472KBBAT4X
designator C?  ValueDisplayed: 4700pF  (hidden comment: VJ1206Y472KBBAT4X)
CAP, CERM, 4700 pF, 100 V,+/- 10%, X7R, 1206; Manufacturer: Vishay-Vitramon; Polarized: N; CompType: Capacitor; Value: 4700pF; U/M: EA; Cap_F: 0.0000000047; Tolerance_%: 10; VDC_V: 100; Value2: 100V; TaMin_C: -55; TaMax_C: 125; Cap_Case: 1206; SizeArea_mm2: 5.12; SizeAreaWB_mm2: 10.92; SizeX_mm: 3.2; SizeY_mm: 1.6; SizeZ_mm: 1.35; AEC Category: Q200
signal-integrity model Cap
simulation model Cap
footprint 1206
footprint 1206M
footprint 1206L
pins: 1, 2

## VJ1206Y472KXEAT5Z
designator C?  ValueDisplayed: 4700pF  (hidden comment: VJ1206Y472KXEAT5Z)
CAP, CERM, 4700 pF, 500 V,+/- 10%, X7R, 1206; Manufacturer: Vishay-Vitramon; Polarized: N; CompType: Capacitor; Value: 4700pF; U/M: EA; Cap_F: 0.0000000047; Tolerance_%: 10; VDC_V: 500; Value2: 500V; TaMin_C: -55; TaMax_C: 125; Cap_Case: 1206; SizeArea_mm2: 5.12; SizeAreaWB_mm2: 10.92; SizeX_mm: 3.2; SizeY_mm: 1.6; SizeZ_mm: 1.35; AEC Category: Q200
signal-integrity model Cap
simulation model Cap
footprint 1206
footprint 1206M
footprint 1206L
pins: 1, 2

## VJ1206Y472KXGAT5Z
designator C?  ValueDisplayed: 4700pF  (hidden comment: VJ1206Y472KXGAT5Z)
CAP, CERM, 4700 pF, 1000 V,+/- 10%, X7R, 1206; Manufacturer: Vishay-Vitramon; Polarized: N; CompType: Capacitor; Value: 4700pF; U/M: EA; Cap_F: 0.0000000047; Tolerance_%: 10; VDC_V: 1000; Value2: 1000V; TaMin_C: -55; TaMax_C: 125; Cap_Case: 1206; SizeArea_mm2: 5.12; SizeAreaWB_mm2: 10.92; SizeX_mm: 3.2; SizeY_mm: 1.6; SizeZ_mm: 1.35; AEC Category: Q200
signal-integrity model Cap
simulation model Cap
footprint 1206
footprint 1206M
footprint 1206L
pins: 1, 2

## VJ1206Y473KBBAT4X
designator C?  ValueDisplayed: 0.047µF  (hidden comment: VJ1206Y473KBBAT4X)
CAP, CERM, 0.047 µF, 100 V,+/- 10%, X7R, 1206; Manufacturer: Vishay-Vitramon; Polarized: N; CompType: Capacitor; Value: 0.047uF; U/M: EA; Cap_F: 0.000000047; Tolerance_%: 10; VDC_V: 100; Value2: 100V; TaMin_C: -55; TaMax_C: 125; Cap_Case: 1206; SizeArea_mm2: 5.12; SizeAreaWB_mm2: 10.92; SizeX_mm: 3.2; SizeY_mm: 1.6; SizeZ_mm: 1.35; AEC Category: Q200
signal-integrity model Cap
simulation model Cap
footprint 1206
footprint 1206M
footprint 1206L
pins: 1, 2

## VJ1206Y473KXEAT5Z
designator C?  ValueDisplayed: 0.047µF  (hidden comment: VJ1206Y473KXEAT5Z)
CAP, CERM, 0.047 µF, 500 V,+/- 10%, X7R, 1206; Manufacturer: Vishay-Vitramon; Polarized: N; CompType: Capacitor; Value: 0.047uF; U/M: EA; Cap_F: 0.000000047; Tolerance_%: 10; VDC_V: 500; Value2: 500V; TaMin_C: -55; TaMax_C: 125; Cap_Case: 1206; SizeArea_mm2: 5.12; SizeAreaWB_mm2: 10.92; SizeX_mm: 3.2; SizeY_mm: 1.6; SizeZ_mm: 1.35; AEC Category: Q200
signal-integrity model Cap
simulation model Cap
footprint 1206
footprint 1206M
footprint 1206L
pins: 1, 2

## VJ1210A100JXGAT5Z
designator C?  ValueDisplayed: 10pF  (hidden comment: VJ1210A100JXGAT5Z)
CAP, CERM, 10 pF, 1000 V,+/- 5%, C0G/NP0, 1210; Manufacturer: Vishay-Vitramon; Polarized: N; CompType: Capacitor; Value: 10pF; U/M: EA; Cap_F: 0.00000000001; Tolerance_%: 5; VDC_V: 1000; Value2: 1000V; TaMin_C: -55; TaMax_C: 125; Cap_Case: 1210; SizeArea_mm2: 8; SizeAreaWB_mm2: 14.7; SizeX_mm: 3.2; SizeY_mm: 2.5; SizeZ_mm: 1.35; AEC Category: Q200
signal-integrity model Cap
simulation model Cap
footprint 1210
footprint 1210M
footprint 1210L
pins: 1, 2

## VJ1210A101JXGAT5Z
designator C?  ValueDisplayed: 100pF  (hidden comment: VJ1210A101JXGAT5Z)
CAP, CERM, 100 pF, 1000 V,+/- 5%, C0G/NP0, 1210; Manufacturer: Vishay-Vitramon; Polarized: N; CompType: Capacitor; Value: 100pF; U/M: EA; Cap_F: 0.0000000001; Tolerance_%: 5; VDC_V: 1000; Value2: 1000V; TaMin_C: -55; TaMax_C: 125; Cap_Case: 1210; SizeArea_mm2: 8; SizeAreaWB_mm2: 14.7; SizeX_mm: 3.2; SizeY_mm: 2.5; SizeZ_mm: 1.35; AEC Category: Q200
signal-integrity model Cap
simulation model Cap
footprint 1210
footprint 1210M
footprint 1210L
pins: 1, 2

## VJ1210A102JXGAT5Z
designator C?  ValueDisplayed: 1000pF  (hidden comment: VJ1210A102JXGAT5Z)
CAP, CERM, 1000 pF, 1000 V,+/- 5%, C0G/NP0, 1210; Manufacturer: Vishay-Vitramon; Polarized: N; CompType: Capacitor; Value: 1000pF; U/M: EA; Cap_F: 0.000000001; Tolerance_%: 5; VDC_V: 1000; Value2: 1000V; TaMin_C: -55; TaMax_C: 125; Cap_Case: 1210; SizeArea_mm2: 8; SizeAreaWB_mm2: 14.7; SizeX_mm: 3.2; SizeY_mm: 2.5; SizeZ_mm: 1.35; AEC Category: Q200
signal-integrity model Cap
simulation model Cap
footprint 1210
footprint 1210M
footprint 1210L
pins: 1, 2

## VJ1210A220JXGAT5Z
designator C?  ValueDisplayed: 22pF  (hidden comment: VJ1210A220JXGAT5Z)
CAP, CERM, 22 pF, 1000 V,+/- 5%, C0G/NP0, 1210; Manufacturer: Vishay-Vitramon; Polarized: N; CompType: Capacitor; Value: 22pF; U/M: EA; Cap_F: 0.000000000022; Tolerance_%: 5; VDC_V: 1000; Value2: 1000V; TaMin_C: -55; TaMax_C: 125; Cap_Case: 1210; SizeArea_mm2: 8; SizeAreaWB_mm2: 14.7; SizeX_mm: 3.2; SizeY_mm: 2.5; SizeZ_mm: 1.35; AEC Category: Q200
signal-integrity model Cap
simulation model Cap
footprint 1210
footprint 1210M
footprint 1210L
pins: 1, 2

## VJ1210A221JXGAT5Z
designator C?  ValueDisplayed: 220pF  (hidden comment: VJ1210A221JXGAT5Z)
CAP, CERM, 220 pF, 1000 V,+/- 5%, C0G/NP0, 1210; Manufacturer: Vishay-Vitramon; Polarized: N; CompType: Capacitor; Value: 220pF; U/M: EA; Cap_F: 0.00000000022; Tolerance_%: 5; VDC_V: 1000; Value2: 1000V; TaMin_C: -55; TaMax_C: 125; Cap_Case: 1210; SizeArea_mm2: 8; SizeAreaWB_mm2: 14.7; SizeX_mm: 3.2; SizeY_mm: 2.5; SizeZ_mm: 1.35; AEC Category: Q200
signal-integrity model Cap
simulation model Cap
footprint 1210
footprint 1210M
footprint 1210L
pins: 1, 2

## VJ1210A222JXGAT5Z
designator C?  ValueDisplayed: 2200pF  (hidden comment: VJ1210A222JXGAT5Z)
CAP, CERM, 2200 pF, 1000 V,+/- 5%, C0G/NP0, 1210; Manufacturer: Vishay-Vitramon; Polarized: N; CompType: Capacitor; Value: 2200pF; U/M: EA; Cap_F: 0.0000000022; Tolerance_%: 5; VDC_V: 1000; Value2: 1000V; TaMin_C: -55; TaMax_C: 125; Cap_Case: 1210; SizeArea_mm2: 8; SizeAreaWB_mm2: 14.7; SizeX_mm: 3.2; SizeY_mm: 2.5; SizeZ_mm: 1.35; AEC Category: Q200
signal-integrity model Cap
simulation model Cap
footprint 1210
footprint 1210M
footprint 1210L
pins: 1, 2

## VJ1210A470JXGAT5Z
designator C?  ValueDisplayed: 47pF  (hidden comment: VJ1210A470JXGAT5Z)
CAP, CERM, 47 pF, 1000 V,+/- 5%, C0G/NP0, 1210; Manufacturer: Vishay-Vitramon; Polarized: N; CompType: Capacitor; Value: 47pF; U/M: EA; Cap_F: 0.000000000047; Tolerance_%: 5; VDC_V: 1000; Value2: 1000V; TaMin_C: -55; TaMax_C: 125; Cap_Case: 1210; SizeArea_mm2: 8; SizeAreaWB_mm2: 14.7; SizeX_mm: 3.2; SizeY_mm: 2.5; SizeZ_mm: 1.35; AEC Category: Q200
signal-integrity model Cap
simulation model Cap
footprint 1210
footprint 1210M
footprint 1210L
pins: 1, 2

## VJ1210A471JXGAT5Z
designator C?  ValueDisplayed: 470pF  (hidden comment: VJ1210A471JXGAT5Z)
CAP, CERM, 470 pF, 1000 V,+/- 5%, C0G/NP0, 1210; Manufacturer: Vishay-Vitramon; Polarized: N; CompType: Capacitor; Value: 470pF; U/M: EA; Cap_F: 0.00000000047; Tolerance_%: 5; VDC_V: 1000; Value2: 1000V; TaMin_C: -55; TaMax_C: 125; Cap_Case: 1210; SizeArea_mm2: 8; SizeAreaWB_mm2: 14.7; SizeX_mm: 3.2; SizeY_mm: 2.5; SizeZ_mm: 1.35; AEC Category: Q200
signal-integrity model Cap
simulation model Cap
footprint 1210
footprint 1210M
footprint 1210L
pins: 1, 2

## VJ1210Y101KXEAT5Z
designator C?  ValueDisplayed: 100pF  (hidden comment: VJ1210Y101KXEAT5Z)
CAP, CERM, 100 pF, 500 V,+/- 10%, X7R, 1210; Manufacturer: Vishay-Vitramon; Polarized: N; CompType: Capacitor; Value: 100pF; U/M: EA; Cap_F: 0.0000000001; Tolerance_%: 10; VDC_V: 500; Value2: 500V; TaMin_C: -55; TaMax_C: 125; Cap_Case: 1210; SizeArea_mm2: 8; SizeAreaWB_mm2: 14.7; SizeX_mm: 3.2; SizeY_mm: 2.5; SizeZ_mm: 1.35; AEC Category: Q200
signal-integrity model Cap
simulation model Cap
footprint 1210
footprint 1210M
footprint 1210L
pins: 1, 2

## VJ1210Y101KXGAT5Z
designator C?  ValueDisplayed: 100pF  (hidden comment: VJ1210Y101KXGAT5Z)
CAP, CERM, 100 pF, 1000 V,+/- 10%, X7R, 1210; Manufacturer: Vishay-Vitramon; Polarized: N; CompType: Capacitor; Value: 100pF; U/M: EA; Cap_F: 0.0000000001; Tolerance_%: 10; VDC_V: 1000; Value2: 1000V; TaMin_C: -55; TaMax_C: 125; Cap_Case: 1210; SizeArea_mm2: 8; SizeAreaWB_mm2: 14.7; SizeX_mm: 3.2; SizeY_mm: 2.5; SizeZ_mm: 1.35; AEC Category: Q200
signal-integrity model Cap
simulation model Cap
footprint 1210
footprint 1210M
footprint 1210L
pins: 1, 2

## VJ1210Y102KXEAT5Z
designator C?  ValueDisplayed: 1000pF  (hidden comment: VJ1210Y102KXEAT5Z)
CAP, CERM, 1000 pF, 500 V,+/- 10%, X7R, 1210; Manufacturer: Vishay-Vitramon; Polarized: N; CompType: Capacitor; Value: 1000pF; U/M: EA; Cap_F: 0.000000001; Tolerance_%: 10; VDC_V: 500; Value2: 500V; TaMin_C: -55; TaMax_C: 125; Cap_Case: 1210; SizeArea_mm2: 8; SizeAreaWB_mm2: 14.7; SizeX_mm: 3.2; SizeY_mm: 2.5; SizeZ_mm: 1.35; AEC Category: Q200
signal-integrity model Cap
simulation model Cap
footprint 1210
footprint 1210M
footprint 1210L
pins: 1, 2

## VJ1210Y102KXGAT5Z
designator C?  ValueDisplayed: 1000pF  (hidden comment: VJ1210Y102KXGAT5Z)
CAP, CERM, 1000 pF, 1000 V,+/- 10%, X7R, 1210; Manufacturer: Vishay-Vitramon; Polarized: N; CompType: Capacitor; Value: 1000pF; U/M: EA; Cap_F: 0.000000001; Tolerance_%: 10; VDC_V: 1000; Value2: 1000V; TaMin_C: -55; TaMax_C: 125; Cap_Case: 1210; SizeArea_mm2: 8; SizeAreaWB_mm2: 14.7; SizeX_mm: 3.2; SizeY_mm: 2.5; SizeZ_mm: 1.35; AEC Category: Q200
signal-integrity model Cap
simulation model Cap
footprint 1210
footprint 1210M
footprint 1210L
pins: 1, 2

## VJ1210Y103KBBAT4X
designator C?  ValueDisplayed: 0.01µF  (hidden comment: VJ1210Y103KBBAT4X)
CAP, CERM, 0.01 µF, 100 V,+/- 10%, X7R, 1210; Manufacturer: Vishay-Vitramon; Polarized: N; CompType: Capacitor; Value: 0.01uF; U/M: EA; Cap_F: 0.00000001; Tolerance_%: 10; VDC_V: 100; Value2: 100V; TaMin_C: -55; TaMax_C: 125; Cap_Case: 1210; SizeArea_mm2: 8; SizeAreaWB_mm2: 14.7; SizeX_mm: 3.2; SizeY_mm: 2.5; SizeZ_mm: 1.35; AEC Category: Q200
signal-integrity model Cap
simulation model Cap
footprint 1210
footprint 1210M
footprint 1210L
pins: 1, 2

## VJ1210Y103KXEAT5Z
designator C?  ValueDisplayed: 0.01µF  (hidden comment: VJ1210Y103KXEAT5Z)
CAP, CERM, 0.01 µF, 500 V,+/- 10%, X7R, 1210; Manufacturer: Vishay-Vitramon; Polarized: N; CompType: Capacitor; Value: 0.01uF; U/M: EA; Cap_F: 0.00000001; Tolerance_%: 10; VDC_V: 500; Value2: 500V; TaMin_C: -55; TaMax_C: 125; Cap_Case: 1210; SizeArea_mm2: 8; SizeAreaWB_mm2: 14.7; SizeX_mm: 3.2; SizeY_mm: 2.5; SizeZ_mm: 1.35; AEC Category: Q200
signal-integrity model Cap
simulation model Cap
footprint 1210
footprint 1210M
footprint 1210L
pins: 1, 2

## VJ1210Y103KXGAT5Z
designator C?  ValueDisplayed: 0.01µF  (hidden comment: VJ1210Y103KXGAT5Z)
CAP, CERM, 0.01 µF, 1000 V,+/- 10%, X7R, 1210; Manufacturer: Vishay-Vitramon; Polarized: N; CompType: Capacitor; Value: 0.01uF; U/M: EA; Cap_F: 0.00000001; Tolerance_%: 10; VDC_V: 1000; Value2: 1000V; TaMin_C: -55; TaMax_C: 125; Cap_Case: 1210; SizeArea_mm2: 8; SizeAreaWB_mm2: 14.7; SizeX_mm: 3.2; SizeY_mm: 2.5; SizeZ_mm: 1.35; AEC Category: Q200
signal-integrity model Cap
simulation model Cap
footprint 1210
footprint 1210M
footprint 1210L
pins: 1, 2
